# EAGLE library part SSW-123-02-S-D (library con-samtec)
THROUGH-HOLE .025" SQ POST SOCKET Source: Samtec SSW.pdf
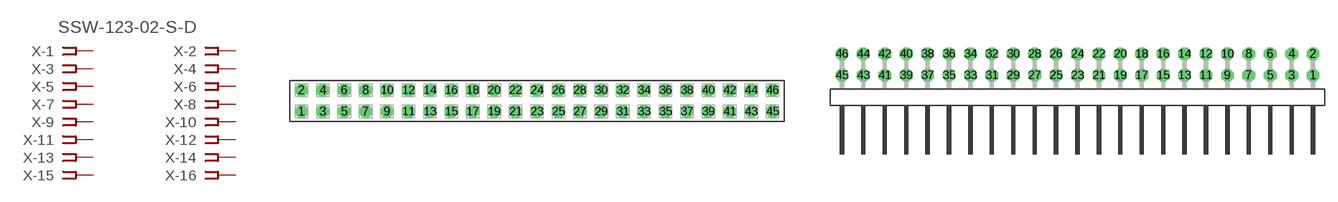
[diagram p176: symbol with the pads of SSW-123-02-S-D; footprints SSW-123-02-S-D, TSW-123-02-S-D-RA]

Designator prefix X; gates -1=FPINV -2=FPIN -3=FPIN -4=FPIN -5=FPIN -6=FPIN -7=FPIN -8=FPIN -9=FPIN -10=FPIN -11=FPIN -12=FPIN -13=FPIN -14=FPIN -15=FPIN -16=FPIN -17=FPIN -18=FPIN -19=FPIN -20=FPIN -21=FPIN -22=FPIN -23=FPIN -24=FPIN -25=FPIN -26=FPIN -27=FPIN -28=FPIN -29=FPIN -30=FPIN -31=FPIN -32=FPIN -33=FPIN -34=FPIN -35=FPIN -36=FPIN -37=FPIN -38=FPIN -39=FPIN -40=FPIN -41=FPIN -42=FPIN -43=FPIN -44=FPIN -45=FPIN -46=FPIN

## SSW-123-02-S-D (MPN: SSW-123-02-S-D; OC_FARNELL: unknown; OC_NEWARK: 11P9690)  [SSW-123-02-S-D]
1  -1:1  pas
2  -2:1  pas
3  -3:1  pas
4  -4:1  pas
5  -5:1  pas
6  -6:1  pas
7  -7:1  pas
8  -8:1  pas
9  -9:1  pas
10  -10:1  pas
11  -11:1  pas
12  -12:1  pas
13  -13:1  pas
14  -14:1  pas
15  -15:1  pas
16  -16:1  pas
17  -17:1  pas
18  -18:1  pas
19  -19:1  pas
20  -20:1  pas
21  -21:1  pas
22  -22:1  pas
23  -23:1  pas
24  -24:1  pas
25  -25:1  pas
26  -26:1  pas
27  -27:1  pas
28  -28:1  pas
29  -29:1  pas
30  -30:1  pas
31  -31:1  pas
32  -32:1  pas
33  -33:1  pas
34  -34:1  pas
35  -35:1  pas
36  -36:1  pas
37  -37:1  pas
38  -38:1  pas
39  -39:1  pas
40  -40:1  pas
41  -41:1  pas
42  -42:1  pas
43  -43:1  pas
44  -44:1  pas
45  -45:1  pas
46  -46:1  pas

## SSW-123-02-S-D-RA (OC_FARNELL: unknown; OC_NEWARK: unknown)  [TSW-123-02-S-D-RA]
Pads as for SSW-123-02-S-D

## Footprint SSW-123-02-S-D (pad centres in mm)
THROUGH-HOLE .025" SQ POST SOCKET Source: Samtec SSW.pdf
drill 1 pad 1.5 octagon: 1 -27.94,-1.27; 2 -27.94,1.27; 3 -25.4,-1.27; 4 -25.4,1.27; 5 -22.86,-1.27; 6 -22.86,1.27; 7 -20.32,-1.27; 8 -20.32,1.27; 9 -17.78,-1.27; 10 -17.78,1.27; 11 -15.24,-1.27; 12 -15.24,1.27; 13 -12.7,-1.27; 14 -12.7,1.27; 15 -10.16,-1.27; 16 -10.16,1.27; 17 -7.62,-1.27; 18 -7.62,1.27; 19 -5.08,-1.27; 20 -5.08,1.27; 21 -2.54,-1.27; 22 -2.54,1.27; 23 0,-1.27; 24 0,1.27; 25 2.54,-1.27; 26 2.54,1.27; 27 5.08,-1.27; 28 5.08,1.27; 29 7.62,-1.27; 30 7.62,1.27; 31 10.16,-1.27; 32 10.16,1.27; 33 12.7,-1.27; 34 12.7,1.27; 35 15.24,-1.27; 36 15.24,1.27; 37 17.78,-1.27; 38 17.78,1.27; 39 20.32,-1.27; 40 20.32,1.27; 41 22.86,-1.27; 42 22.86,1.27; 43 25.4,-1.27; 44 25.4,1.27; 45 27.94,-1.27; 46 27.94,1.27

## Footprint TSW-123-02-S-D-RA (pad centres in mm)
THROUGH-HOLE .025" SQ POST HEADER Source: Samtec TSW.pdf
drill 1 pad 1.5 octagon: 1 27.94,1.524; 2 27.94,4.064; 3 25.4,1.524; 4 25.4,4.064; 5 22.86,1.524; 6 22.86,4.064; 7 20.32,1.524; 8 20.32,4.064; 9 17.78,1.524; 10 17.78,4.064; 11 15.24,1.524; 12 15.24,4.064; 13 12.7,1.524; 14 12.7,4.064; 15 10.16,1.524; 16 10.16,4.064; 17 7.62,1.524; 18 7.62,4.064; 19 5.08,1.524; 20 5.08,4.064; 21 2.54,1.524; 22 2.54,4.064; 23 0,1.524; 24 0,4.064; 25 -2.54,1.524; 26 -2.54,4.064; 27 -5.08,1.524; 28 -5.08,4.064; 29 -7.62,1.524; 30 -7.62,4.064; 31 -10.16,1.524; 32 -10.16,4.064; 33 -12.7,1.524; 34 -12.7,4.064; 35 -15.24,1.524; 36 -15.24,4.064; 37 -17.78,1.524; 38 -17.78,4.064; 39 -20.32,1.524; 40 -20.32,4.064; 41 -22.86,1.524; 42 -22.86,4.064; 43 -25.4,1.524; 44 -25.4,4.064; 45 -27.94,1.524; 46 -27.94,4.064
